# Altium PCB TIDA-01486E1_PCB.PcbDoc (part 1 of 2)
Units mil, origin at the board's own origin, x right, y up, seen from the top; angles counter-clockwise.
Board outline 4100 x 3000 mil, 4 copper layers (Top Layer, Signal Layer 1, Signal Layer 2, Bottom Layer), stack 61.6 mil thick; 140 components, 71 nets, 368 pads, 137 vias.
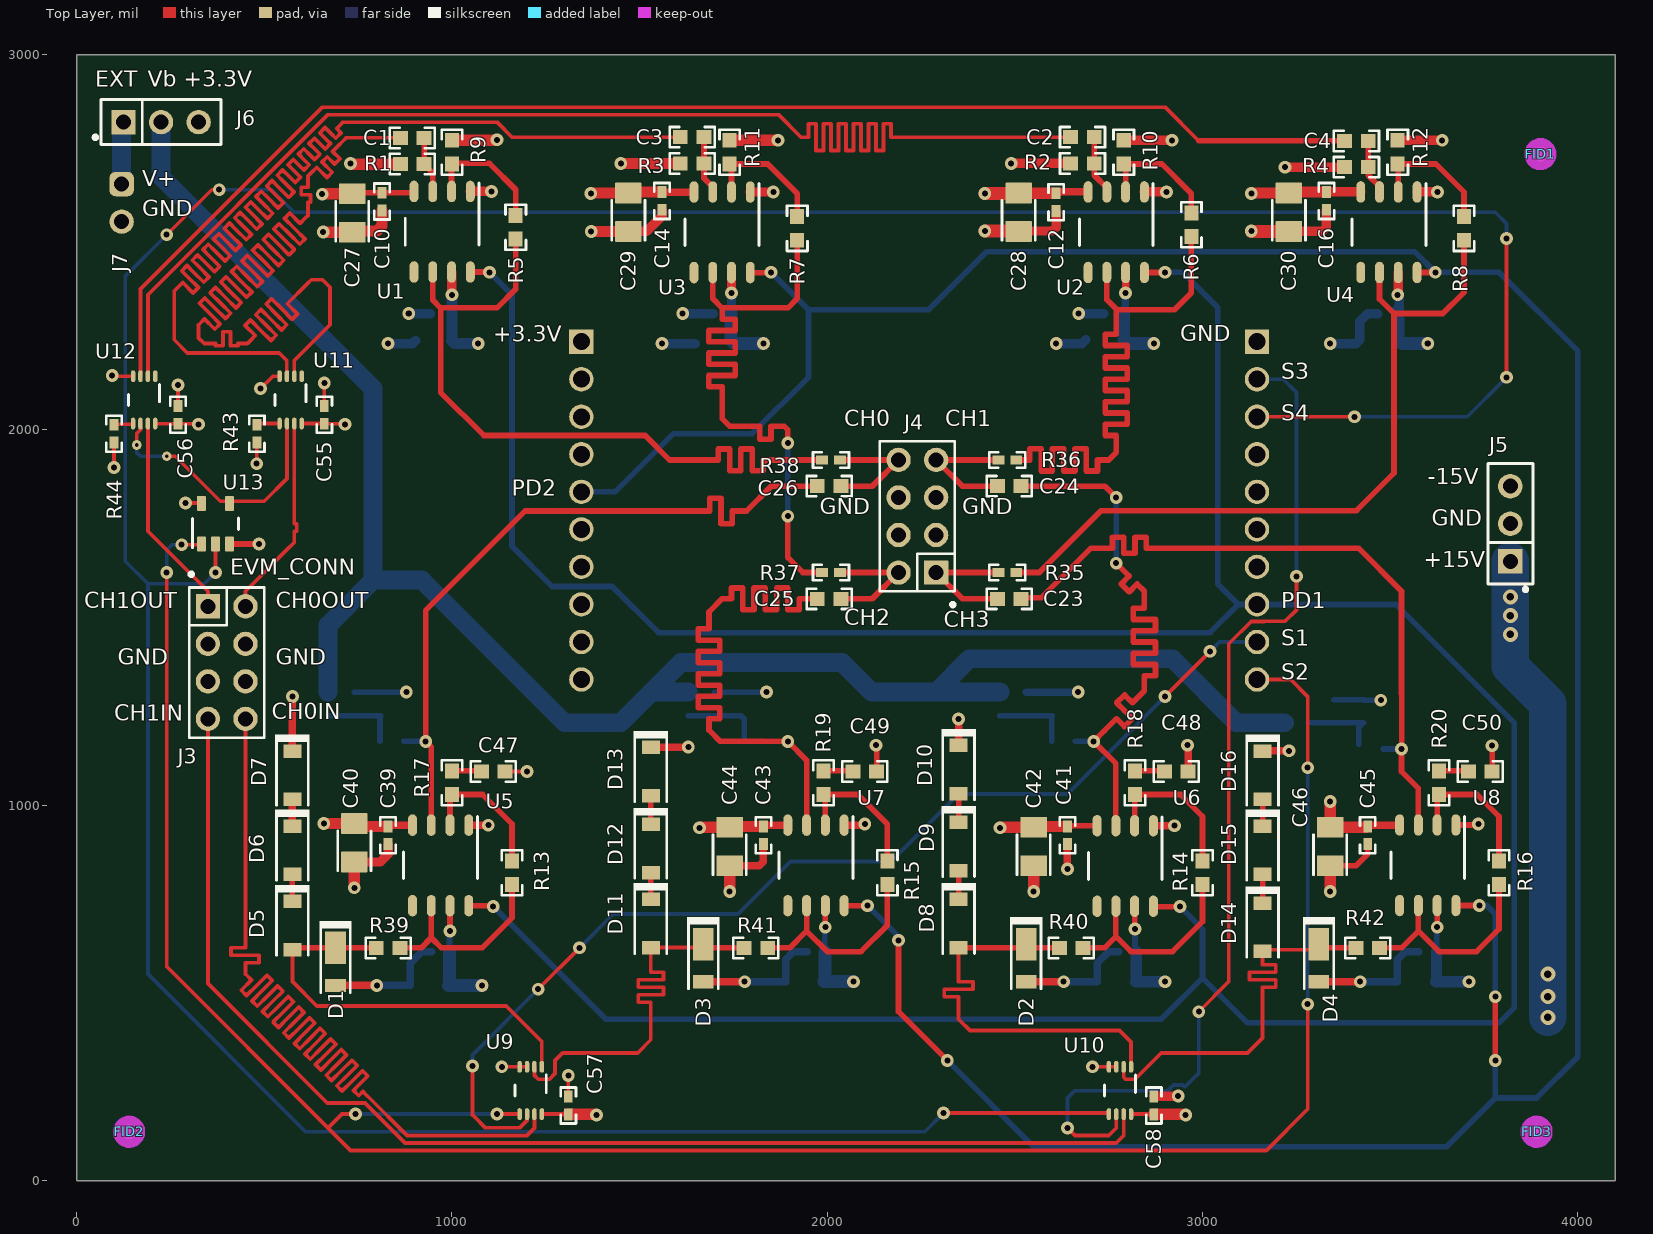
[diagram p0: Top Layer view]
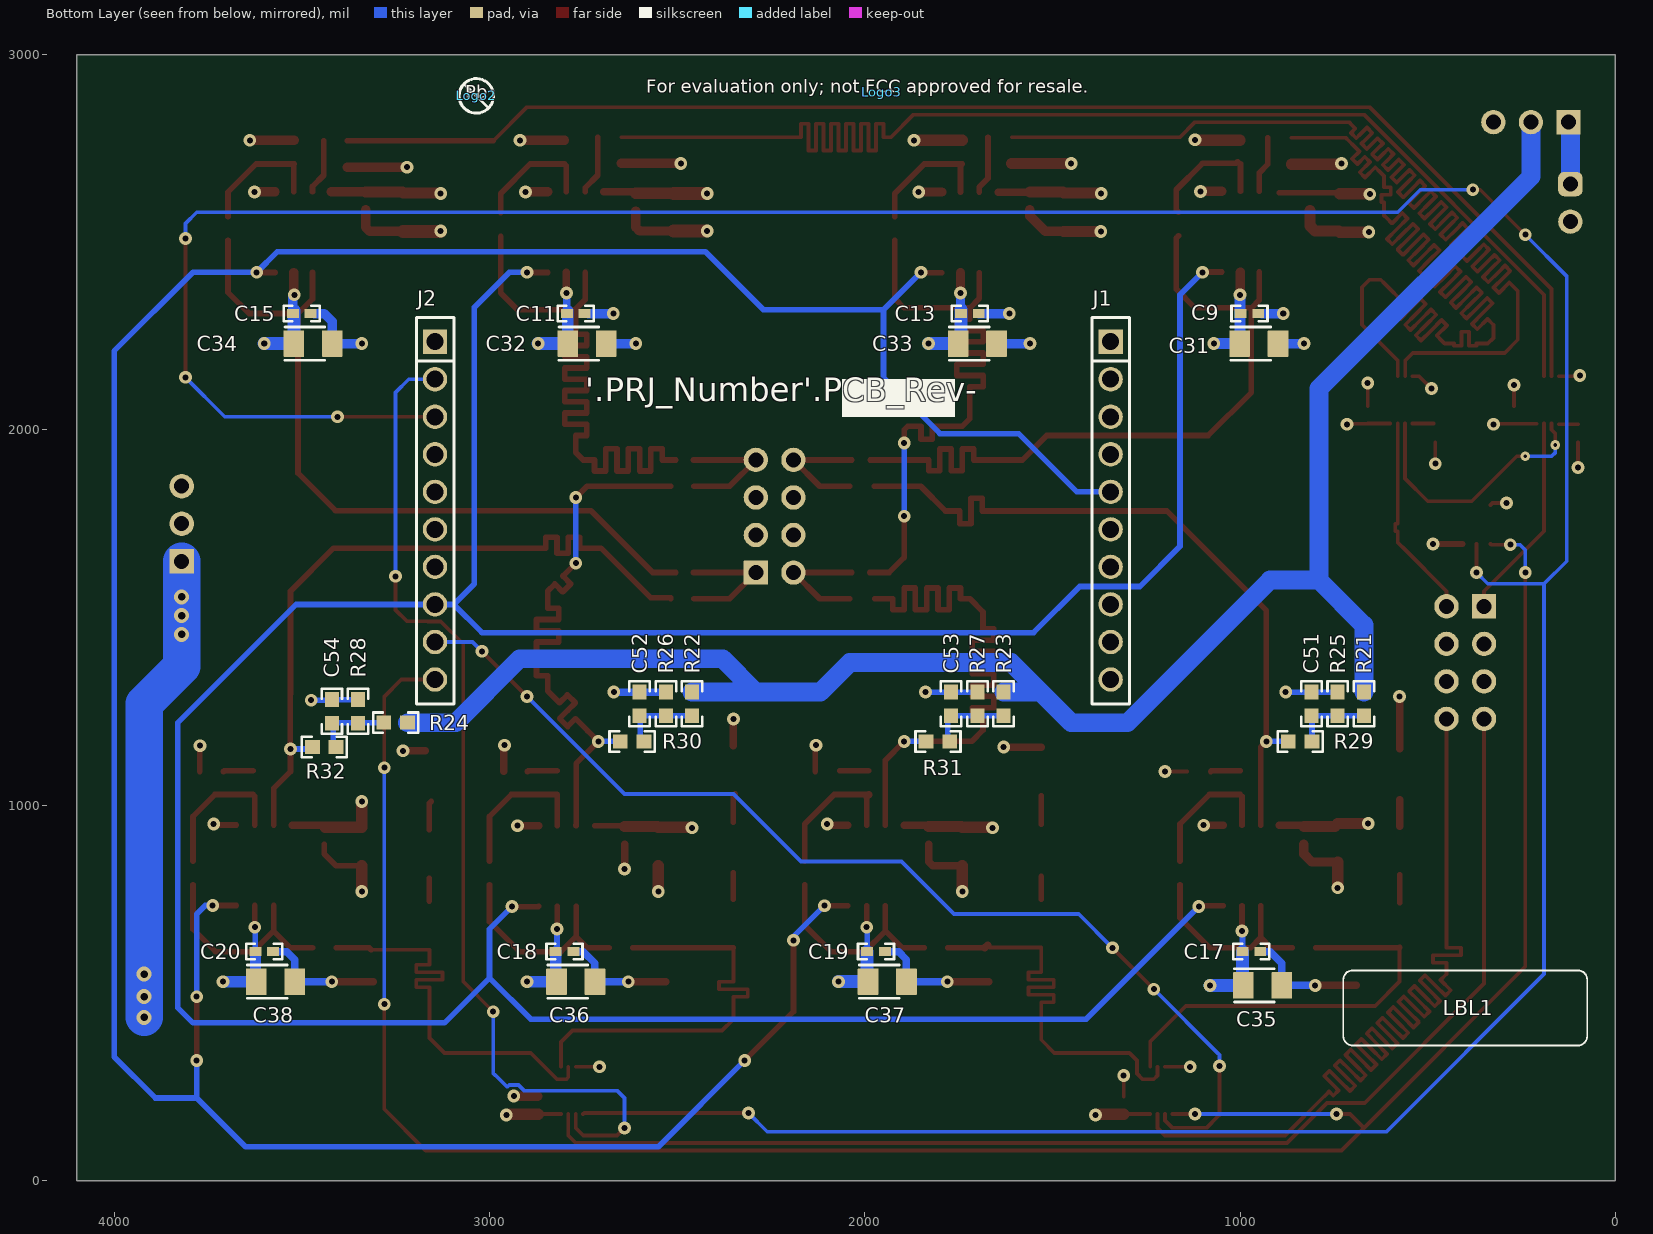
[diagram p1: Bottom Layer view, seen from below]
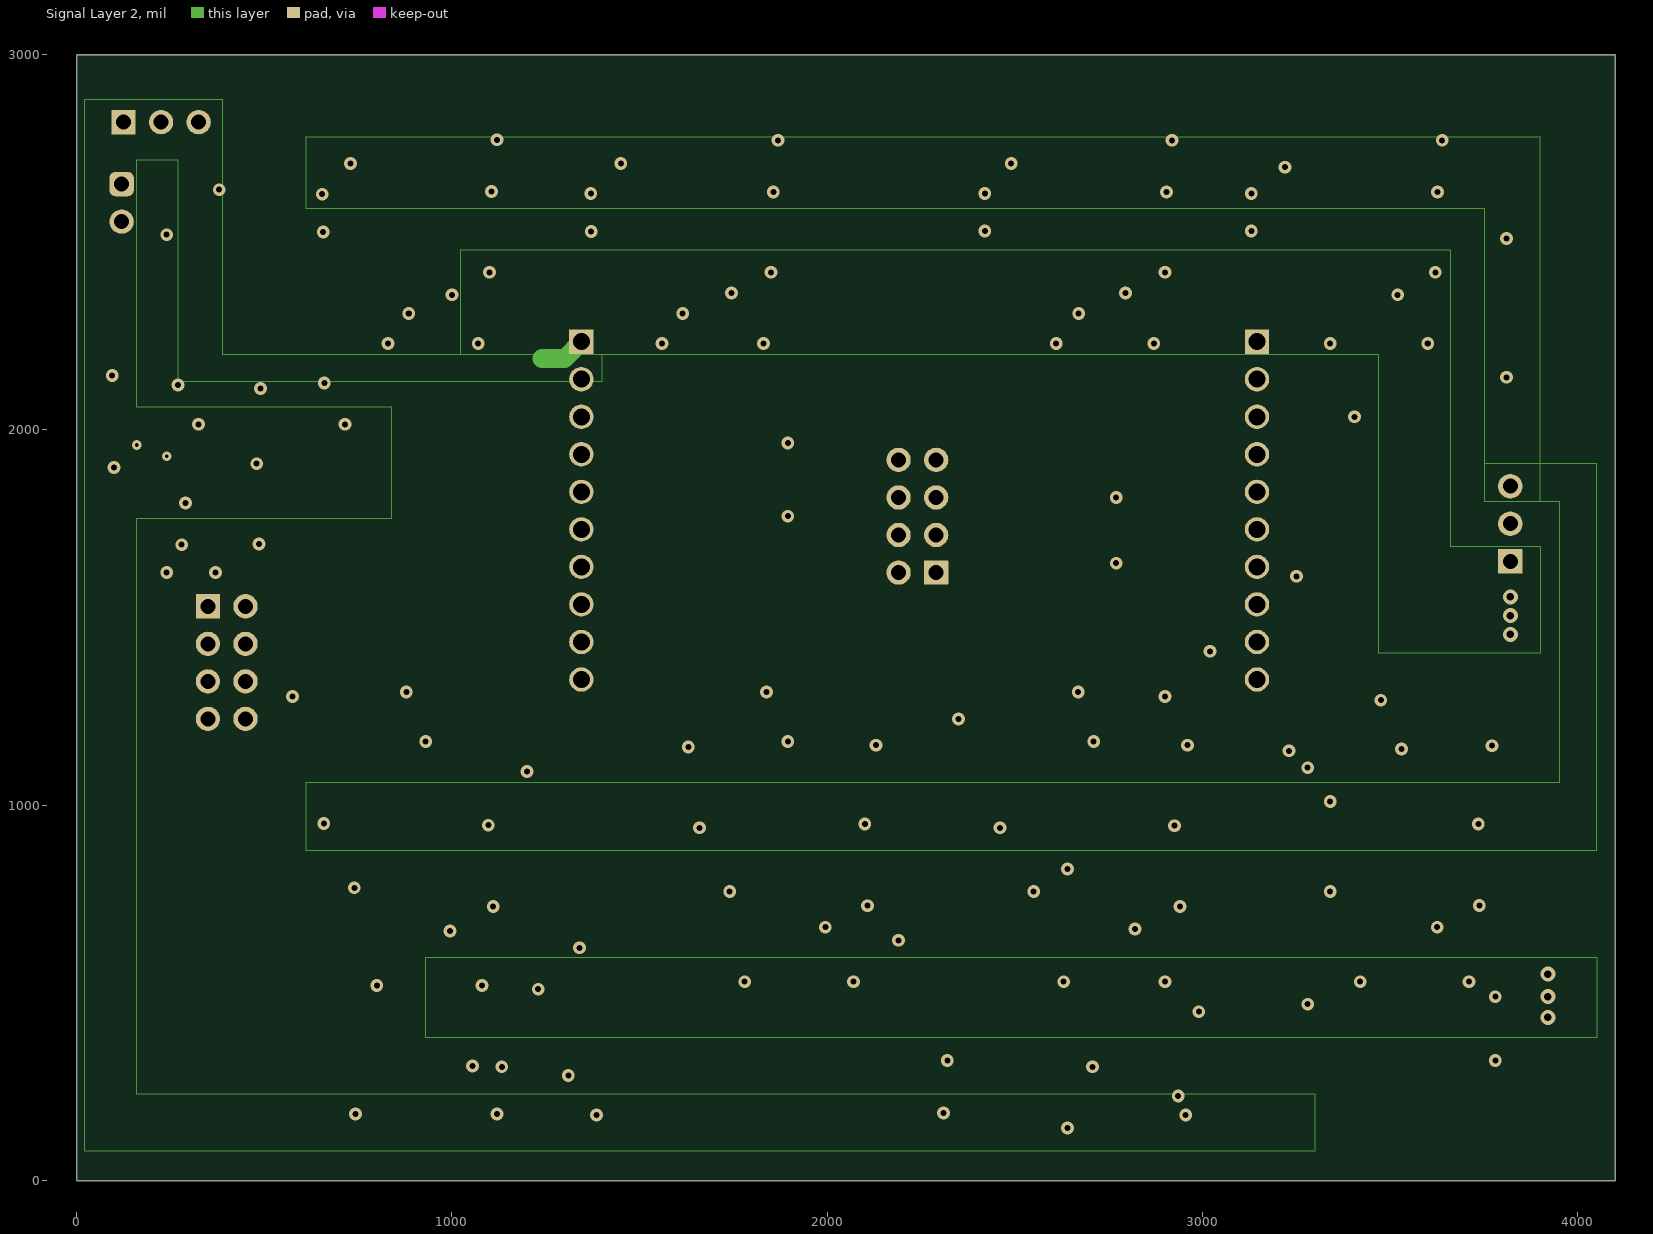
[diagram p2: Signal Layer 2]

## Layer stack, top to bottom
Top Solder: solder mask 0.4, Solder Resist, Dk 3.5
Top Layer: signal copper 1.4
Dielectric 1: prepreg 8, FR-4, Dk 4.2
Signal Layer 1: signal copper 1.4
Dielectric 2: core 40, FR-4, Dk 4.2
Signal Layer 2: signal copper 1.4
Dielectric 3: prepreg 8, FR-4, Dk 4.2
Bottom Layer: signal copper 1.4
Bottom Solder: solder mask 0.4, Solder Resist, Dk 3.5

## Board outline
0,0 4100,0 4100,3000 0,3000

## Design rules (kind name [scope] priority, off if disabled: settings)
AcuteAngle [All] p0: scope1count=1 scope1_0_kind=Board scope1_0_value=Board scope2count=1 scope2_0_kind=Board scope2_0_value=Board commentlength=0 minimum=4.50000000000000E+0001
AcuteAngle [All] p1: minimum=4.50000000000000E+0001 checktracksonly=FALSE
AssemblyTestPointUsage [All] p0: scope1count=1 scope1_0_kind=Board scope1_0_value=Board scope2count=1 scope2_0_kind=Board scope2_0_value=Board commentlength=0
AssemblyTestPointUsage [All] p1: valid=2
AssemblyTestpoint [All] p0: scope1count=1 scope1_0_kind=Board scope1_0_value=Board scope2count=1 scope2_0_kind=Board scope2_0_value=Board commentlength=0
BoardOutlineClearance BoardOutlineClearance_MountingHoles [All] p0 off: scope1count=1 scope1_0_kind=Board scope1_0_value=Board scope2count=1 scope2_0_kind=Board scope2_0_value=Board commentlength=86 gap=40 // Protel DXP Scope 1 Expression Was: OnCopper and InComponentClass('Mounting Holes')
BoardOutlineClearance BoardOutlineClearance_Poly [All] p0 off: scope1count=1 scope1_0_kind=Board scope1_0_value=Board scope2count=1 scope2_0_kind=Board scope2_0_value=Board commentlength=58 gap=25 // Protel DXP Scope 1 Expression Was: OnCopper and IsPoly
BoardOutlineClearance [All] p0 off: scope1count=1 scope1_0_kind=Board scope1_0_value=Board scope2count=1 scope2_0_kind=Board scope2_0_value=Board commentlength=172 gap=75 // Protel DXP Scope 1 Expression Was: OnCopper and Not InComponentClass('Logo') and not InComponentClass('FiducialMark') and not InRegion(1000,500,4000,800) and not InPoly
BoardOutlineClearance BoardOutlineClearance_MountingHoles [OnCopper and InComponentClass('Mounting Holes')] p1: gap=40 ignorepadtopadclearanceinfootprint=FALSE
BoardOutlineClearance BoardOutlineClearance_Poly [OnCopper and IsPoly] p2: gap=25 ignorepadtopadclearanceinfootprint=FALSE
BoardOutlineClearance [OnCopper and Not InComponentClass('Logo') and not InComponentClass('FiducialMark') and not InRegion(1000,500,4000,800) and not InPoly] p3: gap=75 ignorepadtopadclearanceinfootprint=FALSE
Clearance Clearance_Keepouts [All] p0 off: scope1count=1 scope1_0_kind=Board scope1_0_value=Board scope2count=1 scope2_0_kind=Board scope2_0_value=Board commentlength=99 gap=0 // Protel DXP Scope 2 Expression Was: ((IsTrack Or IsArc) And Not InPoly) And IsFree and IsKeepOut
Clearance Clearance_Poly [All] p0 off: scope1count=1 scope1_0_kind=Board scope1_0_value=Board scope2count=1 scope2_0_kind=Board scope2_0_value=Board commentlength=48 gap=21 // Protel DXP Scope 1 Expression Was: InPolygon
Clearance Clearance_FiducialMark [All] p0 off: scope1count=1 scope1_0_kind=Board scope1_0_value=Board scope2count=1 scope2_0_kind=Board scope2_0_value=Board commentlength=81 gap=0 // Protel DXP Scope 2 Expression Was: IsPad and InComponentClass('FiducialMark')
Clearance [All] p0: scope1count=1 scope1_0_kind=Board scope1_0_value=Board scope2count=1 scope2_0_kind=Board scope2_0_value=Board commentlength=0 gap=7.87
Clearance Clearance_Keepouts [((IsTrack Or IsArc) And Not InPoly) And IsFree and IsKeepOut vs ((IsTrack Or IsArc) And Not InPoly) And IsFree and IsKeepOut] p1: gap=0 ignorepadtopadclearanceinfootprint=FALSE
Clearance Clearance_Poly [InPolygon] p2: gap=21 ignorepadtopadclearanceinfootprint=TRUE except(0: Arc-Hole Track-Hole SMDPad-Hole THPad-Hole Via-Hole Fill-Hole Poly-Hole Region-Hole Text-Hole; 10: Arc-Fill Arc-Poly Arc-Region Track-Fill Track-Poly Track-Region SMDPad-Fill SMDPad-Poly SMDPad-Region THPad-Fill THPad-Poly THPad-Region Via-Fill Via-Poly Via-Region Fill-Fill Fill-Poly Fill-Region Poly-Poly Poly-Region Region-Region)
Clearance Clearance_FiducialMark [IsKeepOut and InComponentClass('FiducialMark') vs IsPad and InComponentClass('FiducialMark')] p3: gap=0 ignorepadtopadclearanceinfootprint=FALSE
Clearance [All] p4: gap=7.87 ignorepadtopadclearanceinfootprint=FALSE except(0: Arc-Hole Track-Hole SMDPad-Hole THPad-Hole Via-Hole Fill-Hole Poly-Hole Region-Hole Text-Hole)
ComponentClearance ComponentClearance_MountingHoles_FiducialMarks [All] p0: scope1count=1 scope1_0_kind=ComponentClass scope1_0_value="Mounting Holes" scope2count=1 scope2_0_kind=ComponentClass scope2_0_value=FiducialMark commentlength=0 gap=50 collisioncheckmode=3
ComponentClearance ComponentClearance_Shunt [All] p0: scope1count=1 scope1_0_kind=ComponentClass scope1_0_value=Header scope2count=1 scope2_0_kind=ComponentClass scope2_0_value=Shunt commentlength=0 gap=0 collisioncheckmode=3
ComponentClearance ComponentClearance_Logo [All] p0: scope1count=1 scope1_0_kind=ComponentClass scope1_0_value=Logo scope2count=1 scope2_0_kind=Board scope2_0_value=Board commentlength=0 gap=50 collisioncheckmode=3
ComponentClearance ComponentClearance_ScrewToNut [All] p0 off: scope1count=1 scope1_0_kind=Board scope1_0_value=Board scope2count=1 scope2_0_kind=Board scope2_0_value=Board commentlength=71 gap=5 collisioncheckmode=3 // Protel DXP Scope 2 Expression Was: (HasFootprint('Keystone_1902C'))
ComponentClearance ComponentClearance_MountingHoles [All] p0: scope1count=1 scope1_0_kind=ComponentClass scope1_0_value="Mounting Holes" scope2count=1 scope2_0_kind=Board scope2_0_value=Board commentlength=0 gap=250 collisioncheckmode=3
ComponentClearance ComponentClearance_SmallPassives [All] p0 off: scope1count=1 scope1_0_kind=Board scope1_0_value=Board scope2count=1 scope2_0_kind=Board scope2_0_value=Board commentlength=508 gap=14.96 collisioncheckmode=3 // Protel DXP Scope 2 Expression Was: HasFootprint('0201*') or HasFootprint('0402*') or HasFootprint('0508') or HasFootprint('0603*') or HasFootprint('0612') or HasFootprint('0805*') or HasFootprint('0815*') or HasFootprint('0830*') or HasFootprint('1206*') or HasFootprint('1210*') or HasFootprint('1808*') or HasFootprint('1812*') or HasFootprint('1825*') or HasFootprint('2010*') or HasFootprint('2220*') or HasFootprint('2225*') or HasFootprint('2512*') or HasFootprint('2728*') or HasFootprint('3518*')
ComponentClearance ComponentClearance_THtoSMT [All] p0 off: scope1count=1 scope1_0_kind=Board scope1_0_value=Board scope2count=1 scope2_0_kind=Board scope2_0_value=Board commentlength=53 gap=40 collisioncheckmode=3 // Protel DXP Scope 2 Expression Was: IsSMTComponent
ComponentClearance ComponentClearance_THtoTH [All] p0 off: scope1count=1 scope1_0_kind=Board scope1_0_value=Board scope2count=1 scope2_0_kind=Board scope2_0_value=Board commentlength=54 gap=30 collisioncheckmode=3 // Protel DXP Scope 2 Expression Was: IsThruComponent
ComponentClearance [All] p0: scope1count=1 scope1_0_kind=Board scope1_0_value=Board scope2count=1 scope2_0_kind=Board scope2_0_value=Board commentlength=0 gap=30 collisioncheckmode=3
ComponentClearance ComponentClearance_MountingHoles_FiducialMarks [InComponentClass('Mounting Holes') vs InComponentClass('FiducialMark')] p1: gap=50 collisioncheckmode=3 verticalgap=10 showdistances=FALSE
ComponentClearance ComponentClearance_Shunt [InComponentClass('Header') vs InComponentClass('Shunt')] p2: gap=0 collisioncheckmode=3 verticalgap=0 showdistances=FALSE
ComponentClearance ComponentClearance_Logo [InComponentClass('Logo')] p3: gap=50 collisioncheckmode=3 verticalgap=10 showdistances=FALSE
ComponentClearance ComponentClearance_ScrewToNut [(HasFootprint('NY PMS 440 0025 PH')) vs (HasFootprint('Keystone_1902C'))] p4: gap=5 collisioncheckmode=3 verticalgap=10 showdistances=FALSE
ComponentClearance ComponentClearance_MountingHoles [InComponentClass('Mounting Holes')] p5: gap=250 collisioncheckmode=3 verticalgap=100000 showdistances=FALSE
ComponentClearance ComponentClearance_SmallPassives [HasFootprint('0201*') or HasFootprint('0402*') or HasFootprint('0508') or HasFootprint('0603*') or HasFootprint('0612') or HasFootprint('0805*') or HasFootprint('0815*') or HasFootprint('0830*') or HasFootprint('1206*') or HasFootprint('1210*') or HasFootprint('1808*') or HasFootprint('1812*') or HasFootprint('1825*') or HasFootprint('2010*') or HasFootprint('2220*') or HasFootprint('2225*') or HasFootprint('2512*') or HasFootprint('2728*') or HasFootprint('3518*') vs HasFootprint('0201*') or HasFootprint('0402*') or HasFootprint('0508') or HasFootprint('0603*') or HasFootprint('0612') or HasFootprint('0805*') or HasFootprint('0815*') or HasFootprint('0830*') or HasFootprint('1206*') or HasFootprint('1210*') or HasFootprint('1808*') or HasFootprint('1812*') or HasFootprint('1825*') or HasFootprint('2010*') or HasFootprint('2220*') or HasFootprint('2225*') or HasFootprint('2512*') or HasFootprint('2728*') or HasFootprint('3518*')] p6: gap=14.96 collisioncheckmode=3 verticalgap=10 showdistances=FALSE
ComponentClearance ComponentClearance_THtoSMT [IsThruComponent vs IsSMTComponent] p7: gap=40 collisioncheckmode=3 verticalgap=30 showdistances=FALSE
ComponentClearance ComponentClearance_THtoTH [IsThruComponent vs IsThruComponent] p8: gap=30 collisioncheckmode=3 verticalgap=30 showdistances=FALSE
ComponentClearance [All] p9: gap=30 collisioncheckmode=3 verticalgap=10 showdistances=FALSE
DiffPairsRouting [All] p0: scope1count=1 scope1_0_kind=Board scope1_0_value=Board scope2count=1 scope2_0_kind=Board scope2_0_value=Board commentlength=0
DiffPairsRouting [All] p1: maxlimit=100 minlimit=10 mostfreqgap=10 toplayer_minwidth=15 toplayer_maxwidth=15 toplayer_prefwidth=15 midlayer1_minwidth=15 midlayer1_maxwidth=15 midlayer1_prefwidth=15 midlayer2_minwidth=15 midlayer2_maxwidth=15 midlayer2_prefwidth=15 bottomlayer_minwidth=15 bottomlayer_maxwidth=15 bottomlayer_prefwidth=15 maxuncoupledlength=1000
FabricationTestPointUsage TestPointUsage [All] p0: scope1count=1 scope1_0_kind=Board scope1_0_value=Board scope2count=1 scope2_0_kind=Board scope2_0_value=Board commentlength=0 valid=2 allowmultiple=FALSE
FabricationTestPointUsage TestPointUsage [All] p1: valid=2 allowmultiple=FALSE
FabricationTestpoint Testpoint [All] p0: scope1count=1 scope1_0_kind=Board scope1_0_value=Board scope2count=1 scope2_0_kind=Board scope2_0_value=Board commentlength=0 side=3 testpointundercomponent=TRUE minsize=40 maxsize=100 preferedsize=60 minholesize=0 maxholesize=40 preferedholesize=32 testpointgrid=1
FabricationTestpoint Testpoint [All] p1: side=3 testpointundercomponent=TRUE minsize=40 maxsize=100 preferedsize=60 minholesize=0 maxholesize=40 preferedholesize=32 testpointgrid=1 allowsidetop=TRUE allowsidebottom=TRUE usegrid=TRUE gridtolerance=0.01
FanoutControl Fanout_LCC [All] p0 off: scope1count=1 scope1_0_kind=Board scope1_0_value=Board scope2count=1 scope2_0_kind=Board scope2_0_value=Board commentlength=69 // Protel DXP Scope 1 Expression Was: IsLCC   Fanout_LCC (Default Rule)
FanoutControl Fanout_BGA [All] p0 off: scope1count=1 scope1_0_kind=Board scope1_0_value=Board scope2count=1 scope2_0_kind=Board scope2_0_value=Board commentlength=69 // Protel DXP Scope 1 Expression Was: IsBGA   Fanout_BGA (Default Rule)
FanoutControl Fanout_SOIC [All] p0 off: scope1count=1 scope1_0_kind=Board scope1_0_value=Board scope2count=1 scope2_0_kind=Board scope2_0_value=Board commentlength=71 // Protel DXP Scope 1 Expression Was: IsSOIC   Fanout_SOIC (Default Rule)
FanoutControl Fanout_Default [All] p0: scope1count=1 scope1_0_kind=Board scope1_0_value=Board scope2count=1 scope2_0_kind=Board scope2_0_value=Board commentlength=30 // Fanout_Default (Default Rule)
FanoutControl Fanout_Small [All] p0 off: scope1count=1 scope1_0_kind=Board scope1_0_value=Board scope2count=1 scope2_0_kind=Board scope2_0_value=Board commentlength=84 // Protel DXP Scope 1 Expression Was: (CompPinCount < 5)   Fanout_Small (Default Rule)
FanoutControl Fanout_LCC [IsLCC] p1: bgadir=Out bgaviamode=Centered fanoutstyle=Auto fanoutdirection=Alternating viagrid=1 // Fanout_LCC (Default Rule)
FanoutControl Fanout_BGA [IsBGA] p2: bgadir=Out bgaviamode=Centered fanoutstyle=Auto fanoutdirection=Alternating viagrid=1 // Fanout_BGA (Default Rule)
FanoutControl Fanout_Default [All] p4: bgadir=Out bgaviamode=Centered fanoutstyle=Auto fanoutdirection=Alternating viagrid=1 // Fanout_Default (Default Rule)
FanoutControl Fanout_Small [(CompPinCount < 5)] p5: bgadir=Out bgaviamode=Centered fanoutstyle=Auto fanoutdirection=OutThenIn viagrid=1 // Fanout_Small (Default Rule)
Height [All] p0: scope1count=1 scope1_0_kind=Board scope1_0_value=Board scope2count=1 scope2_0_kind=Board scope2_0_value=Board commentlength=0
HoleSize [All] p0: scope1count=1 scope1_0_kind=Board scope1_0_value=Board scope2count=1 scope2_0_kind=Board scope2_0_value=Board commentlength=0 absolutevalues=TRUE maxlimit=251 minlimit=7.87 maxpercent=80.000 minpercent=20.000
HoleSize [All] p1: absolutevalues=TRUE maxlimit=251 minlimit=7.87 maxpercent=80.000 minpercent=20.000
HoleToHoleClearance [All] p0: scope1count=1 scope1_0_kind=Board scope1_0_value=Board scope2count=1 scope2_0_kind=Board scope2_0_value=Board commentlength=0
LayerPairs [All] p0: scope1count=1 scope1_0_kind=Board scope1_0_value=Board scope2count=1 scope2_0_kind=Board scope2_0_value=Board commentlength=0 enforce=TRUE
MinimumAnnularRing MinimumAnnularRing_ThermalPadVias [All] p0 off: scope1count=1 scope1_0_kind=Board scope1_0_value=Board scope2count=1 scope2_0_kind=Board scope2_0_value=Board commentlength=63 minimumring=5.91 // Protel DXP Scope 1 Expression Was: IsVia and InAnyComponent
MinimumAnnularRing [All] p0: scope1count=1 scope1_0_kind=Board scope1_0_value=Board scope2count=1 scope2_0_kind=Board scope2_0_value=Board commentlength=0 minimumring=8
MinimumAnnularRing MinimumAnnularRing_ThermalPadVias [IsVia and InAnyComponent] p1: minimumring=5.91
MinimumAnnularRing [All] p2: minimumring=8
MinimumSolderMaskSliver MinimumSolderMaskSliver_Logo [All] p0: scope1count=1 scope1_0_kind=ComponentClass scope1_0_value=Logo scope2count=1 scope2_0_kind=ComponentClass scope2_0_value=Logo commentlength=0
MinimumSolderMaskSliver [All] p0: scope1count=1 scope1_0_kind=Board scope1_0_value=Board scope2count=1 scope2_0_kind=Board scope2_0_value=Board commentlength=0
MinimumSolderMaskSliver MinimumSolderMaskSliver_Logo [InComponentClass('Logo') vs InComponentClass('Logo')] p1: minsoldermaskwidth=0.7
MinimumSolderMaskSliver [All] p2: minsoldermaskwidth=3.94
NetAntennae [All] p0: scope1count=1 scope1_0_kind=Board scope1_0_value=Board scope2count=1 scope2_0_kind=Board scope2_0_value=Board commentlength=0
PasteMaskExpansion [All] p0: scope1count=1 scope1_0_kind=Board scope1_0_value=Board scope2count=1 scope2_0_kind=Board scope2_0_value=Board commentlength=0 expansion=0
PlaneClearance [All] p0: scope1count=1 scope1_0_kind=Board scope1_0_value=Board scope2count=1 scope2_0_kind=Board scope2_0_value=Board commentlength=0 clearance=20
PlaneConnect [All] p0: scope1count=1 scope1_0_kind=Board scope1_0_value=Board scope2count=1 scope2_0_kind=Board scope2_0_value=Board commentlength=0 planeconnectstyle=Relief reliefexpansion=10 reliefentries=4 reliefconductorwidth=10 reliefairgap=10
PlaneConnect [All] p1: planeconnectstyle=Relief reliefexpansion=10 reliefentries=4 reliefconductorwidth=10 reliefairgap=10
PolygonConnect [All] p0: scope1count=1 scope1_0_kind=Board scope1_0_value=Board scope2count=1 scope2_0_kind=Board scope2_0_value=Board commentlength=0 connectstyle=Relief reliefconductorwidth=10 reliefentries=4 polygonreliefangle="90 Angle"
PolygonConnect [All] p1: connectstyle=Relief reliefconductorwidth=10 reliefentries=4 polygonreliefangle="90 Angle" airgapwidth=10
RoutingCorners [All] p0: scope1count=1 scope1_0_kind=Board scope1_0_value=Board scope2count=1 scope2_0_kind=Board scope2_0_value=Board commentlength=0 cornerstyle=45-Degree minsetback=100 maxsetback=100
RoutingLayers [All] p0: scope1count=1 scope1_0_kind=Board scope1_0_value=Board scope2count=1 scope2_0_kind=Board scope2_0_value=Board commentlength=0 top layer=Automatic mid layer 1=Automatic mid layer 2=Automatic bottom layer=Automatic
RoutingPriority [All] p0: scope1count=1 scope1_0_kind=Board scope1_0_value=Board scope2count=1 scope2_0_kind=Board scope2_0_value=Board commentlength=0
RoutingTopology [All] p0: scope1count=1 scope1_0_kind=Board scope1_0_value=Board scope2count=1 scope2_0_kind=Board scope2_0_value=Board commentlength=0 topology=Shortest
RoutingVias ThermalPadVias [All] p0 off: scope1count=1 scope1_0_kind=Board scope1_0_value=Board scope2count=1 scope2_0_kind=Board scope2_0_value=Board commentlength=63 holewidth=7.87 width=19.68 viastyle="Through Hole" minholewidth=7.87 minwidth=19.68 maxholewidth=12.99 maxwidth=23.62 // Protel DXP Scope 1 Expression Was: IsVia and InAnyComponent
RoutingVias [All] p0: scope1count=1 scope1_0_kind=Board scope1_0_value=Board scope2count=1 scope2_0_kind=Board scope2_0_value=Board commentlength=0 holewidth=16 width=34 viastyle="Through Hole" minholewidth=7.87 minwidth=26 maxholewidth=40 maxwidth=65
RoutingVias ThermalPadVias [IsVia and InAnyComponent] p1: holewidth=7.87 width=19.68 viastyle="Through Hole" minholewidth=7.87 minwidth=19.68 maxholewidth=12.99 maxwidth=23.62
RoutingVias [All] p2: holewidth=16 width=34 viastyle="Through Hole" minholewidth=7.87 minwidth=26 maxholewidth=40 maxwidth=65
ShortCircuit [All] p0: scope1count=1 scope1_0_kind=Board scope1_0_value=Board scope2count=1 scope2_0_kind=Board scope2_0_value=Board commentlength=0 allowed=FALSE
SilkToBoardRegionClearance [All] p0 off: scope1count=1 scope1_0_kind=Board scope1_0_value=Board scope2count=1 scope2_0_kind=Board scope2_0_value=Board commentlength=130 // Protel DXP Scope 1 Expression Was: Not ((IsComment or IsDesignator) And (Hide <> 'False')) and not InRegion(1000,500,4000,800)
SilkToBoardRegionClearance [Not ((IsComment or IsDesignator) And (Hide <> 'False')) and not InRegion(1000,500,4000,800)] p1:
SilkToSilkClearance SilkToSilkClearance_Pb-FreeLogo [All] p0 off: scope1count=1 scope1_0_kind=Board scope1_0_value=Board scope2count=1 scope2_0_kind=Board scope2_0_value=Board commentlength=120 // Protel DXP Scope 2 Expression Was: (HasFootprint('Pb-Free_Overlay_Medium') OR HasFootprint('Pb-Free_Overlay_Small'))
SilkToSilkClearance [All] p0: scope1count=1 scope1_0_kind=Board scope1_0_value=Board scope2count=1 scope2_0_kind=Board scope2_0_value=Board commentlength=0
SilkToSilkClearance SilkToSilkClearance_Pb-FreeLogo [(HasFootprint('Pb-Free_Overlay_Medium') OR HasFootprint('Pb-Free_Overlay_Small')) vs (HasFootprint('Pb-Free_Overlay_Medium') OR HasFootprint('Pb-Free_Overlay_Small'))] p1: silktosilkclearance=0
SilkToSilkClearance [All] p2: silktosilkclearance=4
SilkToSolderMaskClearance SilkToComponentPadClearance [All] p0 off: scope1count=1 scope1_0_kind=Board scope1_0_value=Board scope2count=1 scope2_0_kind=Board scope2_0_value=Board commentlength=87 // Protel DXP Scope 1 Expression Was: (IsPad or IsFill or IsRegion) and InAnycomponent
SilkToSolderMaskClearance "Silk to Solder Mask Opening" [All] p0: scope1count=1 scope1_0_kind=Board scope1_0_value=Board scope2count=1 scope2_0_kind=Board scope2_0_value=Board commentlength=0
SilkToSolderMaskClearance SilkToComponentPadClearance [(IsPad or IsFill or IsRegion) and InAnycomponent] p1: minsilkscreentomaskgap=3 clearancetoexposedcopper=TRUE
SilkToSolderMaskClearance "Silk to Solder Mask Opening" [All] p2: minsilkscreentomaskgap=4 clearancetoexposedcopper=FALSE
SolderMaskExpansion [All] p0: scope1count=1 scope1_0_kind=Board scope1_0_value=Board scope2count=1 scope2_0_kind=Board scope2_0_value=Board commentlength=0 expansion=1.97
SolderMaskExpansion [All] p1: expansion=1.97 istentingtop=FALSE
UnRoutedNet [All] p0: scope1count=1 scope1_0_kind=Board scope1_0_value=Board scope2count=1 scope2_0_kind=Board scope2_0_value=Board commentlength=0
UnpouredPolygon [All] p0: scope1count=1 scope1_0_kind=Board scope1_0_value=Board scope2count=1 scope2_0_kind=Board scope2_0_value=Board commentlength=0
Width [All] p0: scope1count=1 scope1_0_kind=Board scope1_0_value=Board scope2count=1 scope2_0_kind=Board scope2_0_value=Board commentlength=0 maxlimit=100 minlimit=6 preferedwidth=10
Width [All] p1: maxlimit=100 minlimit=6 preferedwidth=10 checkconnectedcopper=TRUE
15 further rules are at their usual default settings.

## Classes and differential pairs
component class Header: J3 J4 J5 J6 J7
component class TIDA-01486E1_Schematic: C1 C2 C3 C4 C9 C10 C11 C12 C13 C14 C15 C16 C17 C18 C19 C20 C23 C24 C25 C26 C27 C28 C29 C30 C31 C32 C33 C34 C35 C36 C37 C38 C39 C40 C41 C42 C43 C44 C45 C46 C47 C48 C49 C50 C51 C52 C53 C54 C55 C56 C57 C58 D1 D2 D3 D4 D5 D6 D7 D8 D9 D10 D11 D12 D13 D14 D15 D16 J1 J2 J3 J4 J5 J6 J7 R1 R2 R3 R4 R5 R6 R7 R8 R9 R10 R11 R12 R13 R14 R15 R16 R17 R18 R19 R20 R21 R22 R23 R24 R25 R26 R27 R28 R29 R30 R31 R32 R35 R36 R37 R38 R39 R40 R41 R42 R43 R44 U1 U2 U3 U4 U5 U6 U7 U8 U9 U10 U11 U12 U13
component class TIDA-01486E1_Hardware: FID1 FID2 FID3 LBL1 Logo2 Logo3 ZZ1 ZZ2 ZZ3 ZZ4
component class FiducialMark: FID1 FID2 FID3
component class AssemblyNote: ZZ1 ZZ2 ZZ3 ZZ4
component class Label: LBL1

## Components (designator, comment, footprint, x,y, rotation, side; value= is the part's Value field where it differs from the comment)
C1 "GRM188R71H102JA01D" 0603 894.36,2778.15 r180 top
C2 "GRM188R71H102JA01D" 0603 2680,2780 r180 top
C3 "GRM188R71H102JA01D" 0603 1640,2780 r180 top
C4 "GRM188R71H102JA01D" 0603 3410,2770 r180 top
C9 "GRM155R71E104KE14D" 0402 975,2310 r180 bottom
C10 "GRM155R71E104KE14D" 0402 814.04,2608.46 r270 top
C11 "GRM155R71E104KE14D" 0402 2770,2310 r180 bottom
C12 "GRM155R71E104KE14D" 0402 2610,2606.8 r270 top
C13 "GRM155R71E104KE14D" 0402 1720,2310 r180 bottom
C14 "GRM155R71E104KE14D" 0402 1560,2610 r270 top
C15 "GRM155R71E104KE14D" 0402 3500,2310 r180 bottom
C16 "GRM155R71E104KE14D" 0402 3330,2610 r270 top
C17 "GRM155R71E104KE14D" 0402 970,610 r180 bottom
C18 "GRM155R71E104KE14D" 0402 2800,610 r180 bottom
C19 "GRM155R71E104KE14D" 0402 1970,610 r180 bottom
C20 "GRM155R71E104KE14D" 0402 3600,610 r180 bottom
C23 "GRM1885C1H102FA01J" 0603 2485,1550 r0 top
C24 "GRM1885C1H102FA01J" 0603 2485,1850 r0 top
C25 "GRM1885C1H102FA01J" 0603 2005,1550 r0 top
C26 "GRM1885C1H102FA01J" 0603 2005,1850 r0 top
C27 "TPSA685K020R1000" 3216-18 734.36,2578.15 r90 top
C28 "TPSA685K020R1000" 3216-18 2510,2580 r90 top
C29 "TPSA685K020R1000" 3216-18 1470,2580 r90 top
C30 "TPSA685K020R1000" 3216-18 3230,2580 r90 top
C31 "TPSA685K020R1000" 3216-18 950,2230 r180 bottom
C32 "TPSA685K020R1000" 3216-18 2740,2230 r180 bottom
C33 "TPSA685K020R1000" 3216-18 1700,2230 r180 bottom
C34 "TPSA685K020R1000" 3216-18 3470,2230 r180 bottom
C35 "TPSA685K020R1000" 3216-18 940,520 r180 bottom
C36 "TPSA685K020R1000" 3216-18 2770,530 r180 bottom
C37 "TPSA685K020R1000" 3216-18 1940,530 r180 bottom
C38 "TPSA685K020R1000" 3216-18 3570,530 r180 bottom
C39 "GRM155R71E104KE14D" 0402 830,920 r270 top
C40 "TPSA685K020R1000" 3216-18 740,900 r90 top
C41 "GRM155R71E104KE14D" 0402 2640,920 r270 top
C42 "TPSA685K020R1000" 3216-18 2550,890 r90 top
C43 "GRM155R71E104KE14D" 0402 1830,920 r270 top
C44 "TPSA685K020R1000" 3216-18 1740,890 r90 top
C45 "GRM155R71E104KE14D" 0402 3440,920 r270 top
C46 "TPSA685K020R1000" 3216-18 3340,890 r90 top
C47 "GMK107AB7105KAHT" 0603 1110,1090 r0 top
C48 "GMK107AB7105KAHT" 0603 2930,1090 r0 top
C49 "GMK107AB7105KAHT" 0603 2100,1090 r0 top
C50 "GMK107AB7105KAHT" 0603 3740,1090 r0 top
C51 "EMK107BB7225MA-T" 0603 810,1270 r90 bottom
C52 "EMK107BB7225MA-T" 0603 2600,1270 r90 bottom
C53 "EMK107BB7225MA-T" 0603 1770,1270 r90 bottom
C54 "EMK107BB7225MA-T" 0603 3420,1250 r90 bottom
C55 "GRM155R71E104KE14D" 0402 660,2040 r90 top
C56 "GRM155R71E104KE14D" 0402 270,2040 r90 top
C57 "GRM155R71E104KE14D" 0402 1310,200 r90 top
C58 "GRM155R71E104KE14D" 0402 2870,200 r90 top
D1 "DFLS130L-7" PowerDI123 690,570 r270 top
D2 "DFLS130L-7" PowerDI123 2530,580 r270 top
D3 "DFLS130L-7" PowerDI123 1670,580 r270 top
D4 "DFLS130L-7" PowerDI123 3310,580 r270 top
D5 "1N4148W-7-F" SOD-123 575,680 r270 top
D6 "1N4148W-7-F" SOD-123 575,880 r270 top
D7 "1N4148W-7-F" SOD-123 575,1080 r270 top
D8 "1N4148W-7-F" SOD-123 2350,685 r270 top
D9 "1N4148W-7-F" SOD-123 2350,890 r270 top
D10 "1N4148W-7-F" SOD-123 2350,1095 r270 top
D11 "1N4148W-7-F" SOD-123 1530,685 r270 top
D12 "1N4148W-7-F" SOD-123 1530,885 r270 top
D13 "1N4148W-7-F" SOD-123 1530,1090 r270 top
D14 "1N4148W-7-F" SOD-123 3160,675 r270 top
D15 "1N4148W-7-F" SOD-123 3160,880 r270 top
D16 "1N4148W-7-F" SOD-123 3160,1080 r270 top
FID1 "Fiducial" Fiducial10-20 3900,2734.81 r0 top
FID2 "Fiducial" Fiducial10-20 140,130 r0 top
FID3 "Fiducial" Fiducial10-20 3890,130 r0 top
J1 "SSW-110-23-F-S" CONN_SSW-110-23-F-S 1345,1785 r90 bottom
J2 "SSW-110-23-F-S" CONN_SSW-110-23-F-S 3145,1785 r90 bottom
J3 "TSW-104-07-G-D" TSW-104-07-G-D 400,1380 r270 top
J4 "TSW-104-07-G-D" TSW-104-07-G-D 2240,1770 r90 top
J5 "TSW-103-07-G-S" TSW-103-07-X-S 3820,1750 r90 top
J6 "TSW-103-07-G-S" TSW-103-07-X-S 225,2820 r0 top
J7 "TSW-102-07-G-S" TSW-102-07-G-S 120,2605 r270 top
LBL1 "Size: 0.65\" x 0.20 \"" Label_650x200 400,460 r180 bottom
Logo2 "Pb-Free Symbol" Pb-Free_Overlay_Small 3035,2890 r180 bottom
Logo3 "FCC disclaimer" FCC_disclaimer 1955,2900 r180 bottom
R1 "RC0603FR-071KL" 0603 894.36,2708.15 r0 top
R2 "RC0603FR-071KL" 0603 2680,2710 r0 top
R3 "RC0603FR-071KL" 0603 1640,2710 r0 top
R4 "RC0603FR-071KL" 0603 3410,2700 r0 top
R5 "CRCW0603866RFKEA" 0603 1170,2540 r270 top
R6 "CRCW0603866RFKEA" 0603 2970,2546.8 r270 top
R7 "CRCW0603866RFKEA" 0603 1920,2536.8 r270 top
R8 "CRCW0603866RFKEA" 0603 3696.5,2536.8 r270 top
R9 "CRCW060395R3FKEA" 0603 1000,2740 r270 top
R10 "CRCW060395R3FKEA" 0603 2790,2740 r270 top
R11 "CRCW060395R3FKEA" 0603 1740,2740 r270 top
R12 "CRCW060395R3FKEA" 0603 3520,2740 r270 top
R13 "CRCW0603866RFKEA" 0603 1160,820 r270 top
R14 "CRCW0603866RFKEA" 0603 3000,820 r270 top
R15 "CRCW0603866RFKEA" 0603 2160,820 r270 top
R16 "CRCW0603866RFKEA" 0603 3790,820 r270 top
R17 "CRCW060395R3FKEA" 0603 1000,1060 r270 top
R18 "CRCW060395R3FKEA" 0603 2820,1060 r270 top
R19 "CRCW060395R3FKEA" 0603 1990,1060 r270 top
R20 "CRCW060395R3FKEA" 0603 3630,1060 r270 top
R21 "RT0603BRD07100KL" 0603 670,1270 r270 bottom
R22 "RT0603BRD07100KL" 0603 2460,1270 r270 bottom
R23 "RT0603BRD07100KL" 0603 1630,1270 r270 bottom
R24 "RT0603BRD07100KL" 0603 3250,1220 r0 bottom
R25 "RT0603BRD0724K9L" 0603 740,1270 r270 bottom
R26 "RT0603BRD0724K9L" 0603 2530,1270 r270 bottom
R27 "RT0603BRD0724K9L" 0603 1700,1270 r270 bottom
R28 "RT0603BRD0724K9L" 0603 3350.07,1250 r270 bottom
R29 "RMCF0603ZT0R00" 0603 840,1170 r0 bottom
R30 "RMCF0603ZT0R00" 0603 2620,1170 r0 bottom
R31 "RMCF0603ZT0R00" 0603 1805,1170 r0 bottom
R32 "RMCF0603ZT0R00" 0603 3440,1155 r0 bottom
R35 "CRCW0402200RFKED" 0402 2480,1620 r180 top
R36 "CRCW0402200RFKED" 0402 2480,1920 r180 top
R37 "CRCW0402200RFKED" 0402 2010,1620 r180 top
R38 "CRCW0402200RFKED" 0402 2010,1920 r180 top
R39 "CRCW060310R0JNEAHP" 0603 830,620 r180 top
R40 "CRCW060310R0JNEAHP" 0603 2650,620 r180 top
R41 "CRCW060310R0JNEAHP" 0603 1810,620 r180 top
R42 "CRCW060310R0JNEAHP" 0603 3440,620 r180 top
R43 "CRCW040210K0JNED" 0402 480.32,1990 r90 top
R44 "CRCW040210K0JNED" 0402 100,1990 r90 top
U1 "THS3095D" D0008A_N 974.04,2528.15 r270 top
U2 "THS3095D" D0008A_N 2770,2526.8 r270 top
U3 "THS3095D" D0008A_N 1720,2526.49 r270 top
U4 "THS3095D" D0008A_N 3496.5,2526.8 r270 top
U5 "THS3095D" D0008A_N 970,839.68 r270 top
U6 "THS3095D" D0008A_N 2794.04,838.15 r270 top
U7 "THS3095D" D0008A_N 1970,839.68 r270 top
U8 "THS3095D" D0008A_N 3600,840 r270 top
U9 "TS5A3357DCUR" DCU0008A_N 1210,240 r270 top
U10 "TS5A3357DCUR" DCU0008A_N 2780,240 r270 top
U11 "TS5A3357DCUR" DCU0008A_N 570.31,2080 r270 top
U12 "TS5A3357DCUR" DCU0008A_N 180,2080 r270 top
U13 "SN74LVC1G08DBVR" DBV0005A_N 370,1750 r90 top
ZZ1 "This Assembly Note is for PCB labels only" AssemblyNoteLabel 305,5488 r0 top
ZZ2 "This Assembly Note will show in the PcbDoc and associated outputs" AssemblyNote 305,5379.11 r0 top
ZZ3 "This Assembly Note will show in the PcbDoc and associated outputs" AssemblyNote 305,5290.56 r0 top
ZZ4 "This Assembly Note will show in the PcbDoc and associated outputs" AssemblyNote 305,5202 r0 top

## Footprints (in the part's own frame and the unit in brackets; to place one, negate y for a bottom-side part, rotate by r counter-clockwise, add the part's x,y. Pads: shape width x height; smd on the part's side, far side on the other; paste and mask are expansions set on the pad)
0402 [mm] "0402 from SM-752 data"
  rect 0.8x0.6 smd: 1(-0.6,0) 2(0.6,0)
  silkscreen extent -1.22,-0.52 1.22,0.52
0603 [mm] "0603 from SM-752 data"
  rect 1x0.95 smd: 1(-0.8,0) 2(0.8,0)
  silkscreen extent -1.52,-0.69 1.52,0.69
3216-18 [mm] "Based on AVX recommendation in http://www.avx.com/download/software/literature/AVX-Footprint-Library.pdf"
  rrect7% 1.4x1.8 smd: 1(-1.3,0) 2(1.3,0)
  silkscreen extent -1.9,-1.12 0.8,1.12
AssemblyNote [mil] "Assembly Note"
AssemblyNoteLabel [mil] "Assembly Note for PCB Labels"
CONN_SSW-110-23-F-S [mm] "SAMTEC"
  rect 1.65x1.65 hole 1.15: 1(11.43,0)
  round 1.65 hole 1.15: 2(8.89,0) 3(6.35,0) 4(3.81,0) 5(1.27,0) 6(-1.27,0) 7(-3.81,0) 8(-6.35,0) 9(-8.89,0) 10(-11.43,0)
  silkscreen extent -13.08,-1.27 13.08,1.27
D0008A_N [mm] "SOIC, 8-Leads, Body 4.9x3.9mm, Pitch 1.27mm, IPC Medium Density"
  oval 1.45x0.6 smd: 1(-2.725,1.905) 2(-2.725,0.635) 3(-2.725,-0.635) 4(-2.725,-1.905) 5(2.725,-1.905) 6(2.725,-0.635) 7(2.725,0.635) 8(2.725,1.905)
  silkscreen extent -3.3,-2.5 0.9,2.5
DBV0005A_N [mm] "SOT23, 5-Leads, Body 2.9x1.6mm, Pitch 0.95mm, Lead Span 2.8mm, IPC Medium Density"
  rrect17% 1x0.6 smd: 1(-1.375,0.95) 2(-1.375,0) 3(-1.375,-0.95) 4(1.375,-0.95) 5(1.375,0.95)
  silkscreen extent -1.63,-1.55 0.38,1.55
DCU0008A_N [mm] "TSSOP, 8-Leads, Body 2x2.3mm, Pitch 0.5mm, IPC Medium Density"
  oval 0.8x0.3 smd: 1(-1.6,0.75) 2(-1.6,0.25) 3(-1.6,-0.25) 4(-1.6,-0.75) 5(1.6,-0.75) 6(1.6,-0.25) 7(1.6,0.25) 8(1.6,0.75)
  silkscreen extent -1.05,-1.05 0.38,1.05
FCC_disclaimer [mil]
Fiducial10-20 [mm]
  round 1 smd mask+0: 1(0,0)
  Top Layer keep-out circle w1.178: c0,0 r0.5
Label_650x200 [mil] "Thermal Transfer Label"
  silkscreen extent -325,-100 325,100
Pb-Free_Overlay_Small [mil]
  silkscreen extent -46,-46 46,46
PowerDI123 [mm] "Diodes Inc recommended land pattern, document number DS30628 Rev. 6-2"
  rect 2.2x1.4 smd: 1(-1.275,0)
  rect 0.9x1.4 smd: 2(1.275,0)
  silkscreen extent -3.1,-1.09 1.76,1.09
SOD-123 [mm] "On Semi recommended land pattern"
  rect 0.915x1.22 smd: 1(-1.637,0) 2(1.637,0)
  silkscreen extent -2.74,-1.17 2.03,1.17
TSW-102-07-G-S [mm] "Samtec 100mil, 1x2, 230 mil above insulator"
  rrect50% 1.65x1.65 hole 1.016: 1(-1.27,0)
  round 1.65 hole 1.016: 2(1.27,0)
TSW-103-07-X-S [mm] "Samtec Header, 100mil, 1x3"
  rect 1.65x1.65 hole 1.016: 1(-2.54,0)
  round 1.65 hole 1.016: 2(0,0) 3(2.54,0)
  silkscreen extent -4.57,-1.52 4.06,1.52
TSW-104-07-G-D [mm] "Samtec 100mil, 2x4, 230 mil above insulator"
  rrect6% 1.65x1.65 hole 1.016: 1(-3.81,-1.27)
  round 1.65 hole 1.016: 2(-3.81,1.27) 3(-1.27,-1.27) 4(-1.27,1.27) 5(1.27,-1.27) 6(1.27,1.27) 7(3.81,-1.27) 8(3.81,1.27)
  silkscreen extent -6.1,-2.54 5.08,2.54

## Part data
C1 C2 C3 C4: "CAP, CERM, 1000 pF, 50 V,+/- 5%, X7R, 0603"
C9 C10 C11 C12 C13 C14 C15 C16 C17 C18 C19 C20 C39 C41 C43 C45 C55 C56 C57 C58: "CAP, CERM, 0.1 µF, 25 V,+/- 10%, X7R, 0402"
C23 C24 C25 C26: "CAP, CERM, 1000 pF, 50 V,+/- 1%, C0G/NP0, 0603"
C27 C28 C29 C30 C31 C32 C33 C34 C35 C36 C37 C38 C40 C42 C44 C46: "CAP, TA, 6.8 µF, 20 V, +/- 10%, 1 ohm, SMD"
C47 C48 C49 C50: "CAP, CERM, 1 µF, 35 V,+/- 10%, X7R, AEC-Q200 Grade 0, 0603"
C51 C52 C53 C54: "CAP, CERM, 2.2 µF, 16 V,+/- 10%, X7R, 0603"
D1 D2 D3 D4: "Diode, Schottky, 30 V, 1 A, PowerDI123"
D5 D6 D7 D8 D9 D10 D11 D12 D13 D14 D15 D16: library part CMP-0029001-1, "Diode, Ultrafast, 100 V, 0.15 A, SOD-123"
FID1 FID2 FID3: "Fiducial mark.  There is nothing to buy or mount."
J1 J2: library part CMP-0075441-1, "Connector, Receptacle, 100mil, 10x1, Gold plated, TH"
J3 J4: library part CMP-0075408-1, "Header, 100mil, 4x2, Gold, TH"
J5 J6: library part CMP-0075407-1, "Header, 100mil, 3x1, Gold, TH"
J7: library part CMP-0075405-2, "Header, 100mil, 2x1, Gold, TH"
LBL1: library part THT-14-423-10, "Thermal Transfer Printable Labels, 0.650\" W x 0.200\" H - 10,000 per roll"
Logo2: library part Pb-Free
Logo3: library part FCC_disclaimer, "FCC_disclaimer"
R1 R2 R3 R4: "RES, 1.00 k, 1%, 0.1 W, 0603"
R5 R6 R7 R8 R13 R14 R15 R16: "RES, 866, 1%, 0.1 W, 0603"
R9 R10 R11 R12 R17 R18 R19 R20: "RES, 95.3, 1%, 0.1 W, 0603"
R21 R22 R23 R24: "RES, 100 k, 0.1%, 0.1 W, 0603"
R25 R26 R27 R28: "RES, 24.9 k, 0.1%, 0.1 W, 0603"
R29 R30 R31 R32: "RES, 0, 1%, 0.1 W, AEC-Q200 Grade 0, 0603"
R35 R36 R37 R38: "RES, 200, 1%, 0.063 W, 0402"
R39 R40 R41 R42: "RES, 10, 5%, 0.25 W, 0603"
R43 R44: "RES, 10 k, 5%, 0.063 W, 0402"
U1 U2 U3 U4 U5 U6 U7 U8: "Single-High-Voltage, Low Distortion, Current-Feedback Operational Amplifier with Power-Down, 10 to 30 V, -40 to 85 degC, 8-pin SOIC (D8), Green (RoHS & no Sb/Br)"
U9 U10 U11 U12: "Single 5-Ohm SP3T Analog Switch 5-V/3.3-V 3:1 Analog Multiplexer/Demultiplexer, DCU0008A (VSSOP-8)"
U13: "Single 2-Input Positive-AND Gate, DBV0005A, LARGE T&R"
ZZ1: library part AssemblyNoteLabel
ZZ2 ZZ3 ZZ4: library part AssemblyNote

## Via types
v1: diameter 34, hole 16, Top Layer to Bottom Layer, 129 vias
v2: diameter 40, hole 20, Top Layer to Bottom Layer, 6 vias
v3: diameter 26, hole 10, Top Layer to Bottom Layer, 2 vias

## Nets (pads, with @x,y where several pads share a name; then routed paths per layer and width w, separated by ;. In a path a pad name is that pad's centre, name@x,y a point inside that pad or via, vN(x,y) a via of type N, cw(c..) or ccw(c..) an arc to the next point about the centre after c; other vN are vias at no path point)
3.3V: C55.1 C56.1 C57.1 C58.1 J1.1 J6.3 R43.1 R44.1 U9.8 U10.8 U11.8 U12.8 U13.5 | length 788.6
  Top Layer w10: v1(100,1900) R44.1@100,1966.38 ; U12.8@210.47,2016.38 285,2016.38 v1@328.62,2016.38 ; v1(290,1805) 327.6,1805 U13.5@332.6,1800 ; v1(480,1910) 480.32,1910.32 R43.1@480.32,1966.37 ; U11.8@599.84,2017.01 659.37,2017.01 C55.1@660,2016.38 v1@706.38,2016.38 ; U9.8@1239.53,177.01 C57.1@1309.37,177.01 ; U10.8@2809.53,177.01 C58.1@2869.37,177.01
  Top Layer w30: C57.1@1310,176.38 v1@1376.38,176.38 ; C58.1@2870,176.38 v1@2946.38,176.38
  Signal Layer 2 w50: 1240,2190 1300,2190 J1.1@1345,2235
  other v1: 1385,175 2955,175 325,2015 715,2015
+15V: C9.1 C11.1 C13.1 C15.1 C17.1 C18.1 C19.1 C20.1 C31.1 C32.1 C33.1 C34.1 C35.1 C36.1 C37.1 C38.1 J5.1 U1.7 U2.7 U3.7 U4.7 U5.7 U6.7 U7.7 U8.7 | length 3447.9
  Top Layer w15: v1(995,665) U5.7@995,732.4 ; v1(1995,675) U7.7@1995,732.4 ; v1@2819.04,670.96 U6.7@2819.04,730.87 ; v1(3625,675) U8.7@3625,732.72
  Top Layer w20: v1@2795,2375 U2.7@2795,2419.52
  Top Layer w25: U1.7@999.04,2420.87 1000,2419.91 v1(1000,2360) ; v1(1745,2365) U3.7@1745,2419.2 ; v1@3521.5,2371.5 U4.7@3521.5,2419.52
  Bottom Layer w15: C17.1@993.62,610 v1@993.62,663.62 ; C19.1@1993.62,610 v1@1993.62,673.62 ; C18.1@2820.12,610.5 v1@2820.12,666.88 ; C20.1@3623.62,610 v1@3623.62,673.62
  Bottom Layer w20: C11.1@2793.62,2320 v1@2793.62,2363.62
  Bottom Layer w25: C13.1@1745,2308.62 v1(1745,2365) ; C15.1@3523.62,2310 v1@3523.62,2356.38
  Bottom Layer w30: v1(1000,2360) 1000,2239.11 999.04,2238.15 1007.19,2230 v1(1070,2230) ; C32.1@2791.18,2240 C11.1@2791.18,2317.56 ; C18.1@2823.62,610 2823.62,532.44 C36.1@2821.18,530 v1(2900,530) ; C20.1@3623.62,610 3623.62,532.44 C38.1@3621.18,530 v1(3710,530)
  Bottom Layer w35: C17.1@993.62,610 993.62,522.44 C35.1@991.18,520 v1(1080,520) ; C13.1@1743.62,2320 1743.62,2240 1753.62,2230 v1(1830,2230) ; C19.1@1993.62,610 1993.62,532.44 C37.1@1991.18,530 v1(2070,530) ; C32.1@2791.18,2240 2801.18,2230 v1(2870,2230) ; C15.1@3521.18,2317.56 3521.18,2240 3531.18,2230 v1(3600,2230)
  Bottom Layer w100: J5.1@3820,1650 3820,1370 3920,1270 v2(3920,435)
  other v1: 2820,670 3520,2360 2795,2365
  other v2: 3920,490 3920,550 3820,1455 3820,1505 3820,1555
-15V: C10.1 C12.1 C14.1 C16.1 C27.2 C28.2 C29.2 C30.2 C39.1 C40.2 C41.1 C42.2 C43.1 C44.2 C45.1 C46.2 J5.3 U1.4 U2.4 U3.4 U4.4 U5.4 U6.4 U7.4 U8.4 | length 2096.2
  Top Layer w15: C27.2@716.48,2632.09 C10.1@814.04,2632.09 U1.4@895.7,2632.09 ; C41.1@2640,943.62 2641.81,945.43 U6.4@2719.04,945.43
  Top Layer w20: C40.2@740,951.18 C40.2@747.56,943.62 ; C39.1@830,943.62 833.35,946.97 U5.4@895,946.97 ; C14.1@1560,2633.62 1560.15,2633.77 U3.4@1645,2633.77 ; C43.1@1830,943.62 1833.35,946.97 U7.4@1895,946.97 ; C12.1@2610,2630.42 2613.66,2634.09 U2.4@2695,2634.09 ; C45.1@3437.56,941.18 C45.1@3440,943.62 3443.66,947.28 U8.4@3525,947.28
  Top Layer w25: C16.1@3330,2633.62 3330.46,2634.09 U4.4@3421.5,2634.09
  Top Layer w30: v1(654.36,2628.15) 655.54,2629.33 C27.2@734.36,2629.33 ; v1(658.82,951.18) C40.2@740,951.18 ; C40.2@747.56,943.62 C39.1@830,943.62 ; v1(1370,2630) 1371.18,2631.18 C29.2@1470,2631.18 ; C29.2@1472.44,2633.62 C14.1@1560,2633.62 ; v1@1661.18,941.18 C44.2@1740,941.18 1742.44,943.62 C43.1@1830,943.62 ; v1@2461.18,941.18 C42.2@2550,941.18 2552.44,943.62 C41.1@2640,943.62 ; C28.2@2508.82,2630 C28.2@2510,2631.18 2510.76,2630.42 C12.1@2610,2630.42 ; v1(3130,2630) 3131.18,2631.18 C30.2@3230,2631.18 3232.44,2633.62 C16.1@3330,2633.62 ; v1(3340,1010) C46.2@3340,941.18 C45.1@3437.56,941.18
  Top Layer w35: v1(2420,2630) C28.2@2508.82,2630
  other v1: 1660,940 2460,940
CH0_IN: C26.1 R29.2 U5.3 | length 1955.1
  Top Layer w15: U5.3@945,946.97 945,1155 v1(930,1170) 930,1519 1195,1784 1548,1784 1687,1784 1687,1818.07 1717,1818.07 1717,1784 1717,1749.93 1747,1749.93 1747,1784 1762,1784 1785,1784 1851,1850 C26.1@1973.5,1850 C26.1@1975,1850
  Bottom Layer w15: R29.2@871.5,1170 v1(930,1170)
CH0_OUT: R5.2 R38.2 U1.6 | length 2015.3
  Top Layer w15: U1.6@949.04,2420.87 949.04,2345.96 970,2325 ; R5.2@1164.04,2516.97 R5.2@1170,2511.01 ; R5.2@1170,2508.5 1170,2375 1120,2325 970,2325 ; R38.2@1985,1920 1845,1920 1830,1920 1830,1890.8 1800,1890.8 1800,1920 1800,1949.2 1770,1949.2 1770,1920 1770,1890.8 1740,1890.8 1740,1920 1740,1949.2 1710,1949.2 1710,1920 1620,1920 1580,1920 1515,1985 1085,1985 970,2100 970,2325
CH0_R: D1.1 D5.2 R39.2 U9.1 | length 1112.6
  Top Layer w10: D5.2@575,621.01 575,530 640,465 1145,465 1239.53,370.47 U9.1@1239.53,302.99
  Top Layer w15: D5.2@575,621.01 D1.1@690,620.2 R39.2@798.5,620.2
CH0_T: C1.2 U11.2 | length 3678.7
  Top Layer w10: U11.2@580,2143 U11.2@580.16,2143.15 ; U11.2@580.16,2142.99 U11.2@580.16,2143.15 ; 585,2190 675,2280 675,2380 655,2400 625,2400 615,2390 561.07,2336.07 588.43,2308.7 574.29,2294.56 546.92,2321.92 519.56,2349.29 505.42,2335.15 532.78,2307.78 560.15,2280.42 546,2266.28 518.64,2293.64 491.28,2321 477.13,2306.86 504.5,2279.5 531.86,2252.13 517.72,2237.99 490.36,2265.36 462.99,2292.72 448.85,2278.58 476.21,2251.21 462.07,2237.07 455,2230 450,2230 430,2230 430,2224.17 410,2224.17 410,2230 410,2261.86 390,2261.86 390,2230 390,2224.17 370,2224.17 370,2230 350,2230 340,2230 325,2245 325,2280 326.62,2281.62 340.76,2295.76 368.13,2268.4 382.27,2282.54 354.9,2309.9 327.54,2337.27 341.68,2351.41 369.05,2324.05 396.41,2296.68 410.55,2310.82 383.19,2338.19 355.82,2365.55 369.97,2379.69 397.33,2352.33 424.69,2324.97 438.84,2339.11 411.47,2366.47 384.11,2393.84 398.25,2407.98 425.62,2380.62 452.98,2353.25 467.12,2367.39 439.76,2394.76 412.39,2422.12 426.54,2436.26 453.9,2408.9 481.26,2381.54 495.41,2395.68 468.04,2423.04 440.68,2450.41 454.82,2464.55 482.18,2437.18 509.55,2409.82 523.69,2423.96 496.33,2451.33 468.96,2478.69 483.1,2492.83 510.47,2465.47 537.83,2438.1 551.97,2452.25 524.61,2479.61 497.25,2506.97 511.39,2521.12 538.75,2493.75 566.12,2466.39 580.26,2480.53 552.89,2507.89 525.53,2535.26 539.67,2549.4 567.04,2522.04 594.4,2494.67 608.54,2508.81 581.18,2536.18 553.81,2563.54 567.96,2577.68 595.32,2550.32 609.46,2564.46 616.53,2571.53 616.53,2586.53 616.53,2606.53 623.23,2606.53 623.23,2626.53 616.53,2626.53 598.43,2626.53 598.43,2646.53 616.53,2646.53 616.53,2666.53 616.53,2676.53 625.58,2685.58 639.72,2699.72 667.08,2672.35 681.22,2686.5 653.86,2713.86 668,2728 687.47,2708.53 701.62,2722.67 682.14,2742.14 696.29,2756.29 710.43,2770.43 717.5,2777.5 718.15,2778.15 C1.2@862.86,2778.15 ; 585.08,2189.92 580.16,2185 U11.2@580.16,2143.15
CH1_IN: C24.2 R30.2 U6.3 | length 1834.7
  Top Layer w15: C24.2@2516.5,1850 2740,1850 v1(2770,1820) ; U6.3@2770,946.39 U6.3@2769.04,945.43 2769.04,1110.96 v1(2710,1170) 2737.5,1197.5 2770.75,1230.75 2791.69,1209.82 2812.9,1231.03 2791.97,1251.97 2771.03,1272.9 2792.24,1294.12 2813.18,1273.18 2834.39,1294.39 2845,1305 2845,1315 2845,1345 2874.61,1345 2874.61,1375 2845,1375 2815.39,1375 2815.39,1405 2845,1405 2874.61,1405 2874.61,1435 2845,1435 2815.39,1435 2815.39,1465 2845,1465 2874.61,1465 2874.61,1495 2845,1495 2815.39,1495 2815.39,1525 2845,1525 2845,1555 2845,1570 2825.53,1589.47 2804.6,1568.53 2783.38,1589.75 2804.32,1610.68 2783.11,1631.89 2772.5,1642.5 v1(2770,1645)
  Bottom Layer w15: R30.2@2661.5,1170 v1(2710,1170) ; v1(2770,1645) v1(2770,1820)
CH1_OUT: R6.2 R36.1 U2.6 | length 2015.3
  Top Layer w15: R36.1@2503.62,1920 2525,1920 2540,1920 2540,1949.43 2570,1949.43 2570,1920 2570,1890.57 2600,1890.57 2600,1920 2600,1949.43 2630,1949.43 2630,1920 2630,1890.57 2660,1890.57 2660,1920 2660,1949.43 2690,1949.43 2690,1920 2690,1890.57 2720,1890.57 2720,1920 2750,1920 2770,1940 2770,1955 2770,1985 2740.57,1985 2740.57,2015 2770,2015 2799.43,2015 2799.43,2045 2770,2045 2740.57,2045 2740.57,2075 2770,2075 2799.43,2075 2799.43,2105 2770,2105 2740.57,2105 2740.57,2135 2770,2135 2799.43,2135 2799.43,2165 2770,2165 2740.57,2165 2740.57,2195 2770,2195 2799.43,2195 2799.43,2225 2770,2225 2740.57,2225 2740.57,2255 2770,2255 2770,2290 2770,2320 ; U2.6@2745,2419.52 2745,2346.65 2771.65,2320 2925,2320 2970,2365 R6.2@2970,2515.31
CH1_R: D2.1 D8.2 R40.2 U10.1 | length 1162.8
  Top Layer w10: D8.2@2350,620.2 2350,540 2350,530 2388.22,530 2388.22,510 2350,510 2311.78,510 2311.78,490 2350,490 2350,470 2350,430 2380,400 2779.06,400 2809.53,369.53 U10.1@2809.53,302.99
  Top Layer w15: D8.2@2350,620.2 2530,620.2 2530.2,620 R40.2@2618.5,620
